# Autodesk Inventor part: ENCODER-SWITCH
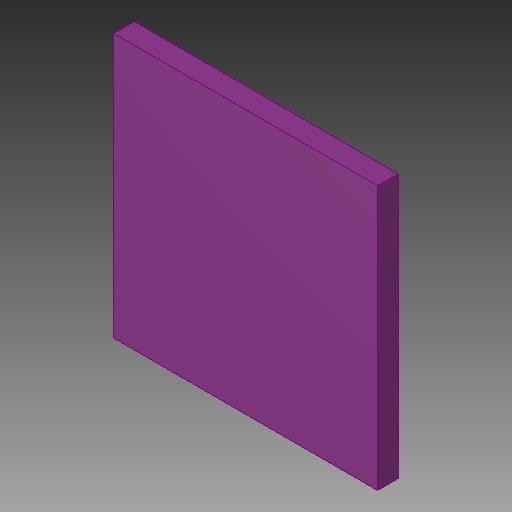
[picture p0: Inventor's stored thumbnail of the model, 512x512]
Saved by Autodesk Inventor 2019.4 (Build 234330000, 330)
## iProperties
Created: 2019-11
Part Number: ENCODER-SWITCH
Material: Generic
Document SubType Name: Modeling
Designer: Willist
Density: 1 g/cm^3
Appearance: ROTARY_ENC_PLAIN, ENCODER-SWITCH
Author: Willist
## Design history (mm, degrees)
sketch "ROTARY_ENC_PLAIN, ENCODER-SWITCH_12"
  geometry: L1 (-6.452, 6.452)-(6.35, 6.452); L2 (6.35, 6.452)-(6.35, -6.35); L3 (6.35, -6.35)-(-6.452, -6.35); L4 (-6.452, -6.35)-(-6.452, 6.452)
  constraints: 8 end point
extrude "Extrusion1" join sketch "ROTARY_ENC_PLAIN, ENCODER-SWITCH_12" distance "d0" = 1; taper "d1" = 0 deg
body "Solid1"
